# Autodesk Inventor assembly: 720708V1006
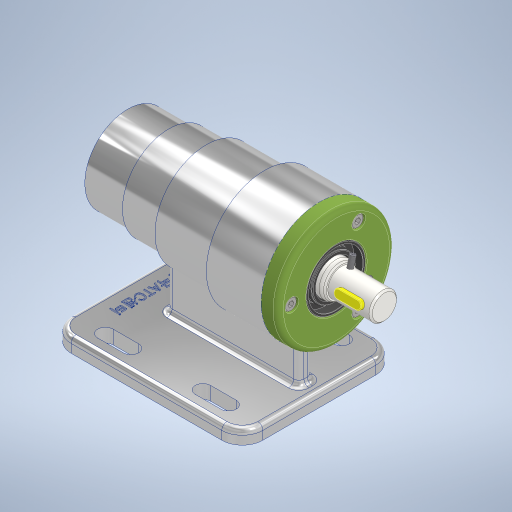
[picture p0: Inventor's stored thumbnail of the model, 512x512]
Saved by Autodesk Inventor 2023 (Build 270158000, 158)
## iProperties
Created: 2022-07
Part Number: 720708V1006
Document SubType Name: Assembly
Designer: owner
Author: owner
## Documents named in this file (12)
- C:\Users\owner\Desktop\720708V1006\720708V1006.iam
- C:\Users\owner\Desktop\720708V1006\본체.ipt
- C:\Users\owner\Desktop\720708V1006\V벨트풀리.ipt
- C:\Users\owner\Desktop\720708V1006\멈춤나사 M3.ipt
- C:\Users\owner\Desktop\720708V1006\베어링 6004.ipt
- C:\Users\owner\Desktop\720708V1006\베어링 51202.ipt
- C:\Users\owner\Desktop\720708V1006\볼트 M4.ipt
- C:\Users\owner\Desktop\720708V1006\어댑터슬리브.ipt
- C:\Users\owner\Desktop\720708V1006\오일 실 20x35x7.ipt
- C:\Users\owner\Desktop\720708V1006\축.ipt
- C:\Users\owner\Desktop\720708V1006\커버.ipt
- C:\Users\owner\Desktop\720708V1006\키 5x5.ipt
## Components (1 placed, 1 different names)
1. V벨트풀리:1 — 강체:3
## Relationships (1: WeldJoint 1)
- 강체:3 [WeldJoint]: V벨트풀리:1
